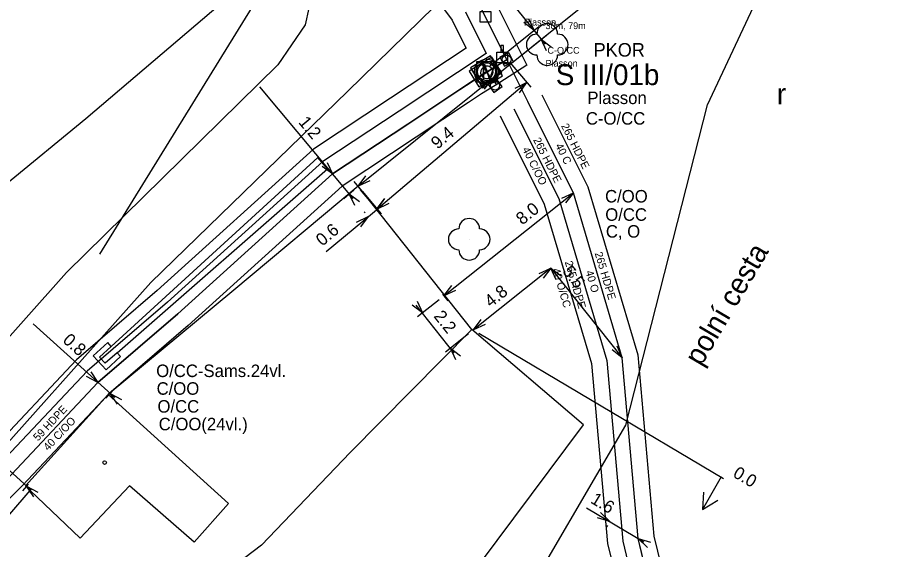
# Model space of a CAD drawing. Extents: x -836739 to -834468, y -1071001 to -1070126.
# Drawn here: x -836480.21 to -836438.65, y -1070294.18 to -1070268.59 of the extents above; entities that cross this region are included whole.
import ezdxf

# ---------------------------------------------------------------- set-up
doc = ezdxf.new("R2010")
doc.units = 0
for name, color, linetype in [('f001_pol_linie', 7, 'Continuous'), ('f001_pol_texty', 7, 'Continuous'), ('f001_pol_znacky', 7, 'Continuous'), ('f002_inz_linie_mimo_CETIN', 7, 'Continuous'), ('f003_opt_sit_texty', 7, 'Continuous'), ('f003_opt_sit_znacky', 7, 'Continuous'), ('f006_kbv_texty', 7, 'Continuous'), ('f006_kbv_znacky', 7, 'Continuous'), ('f006_osa_trasy', 7, 'Continuous'), ('f006_stp_koty', 7, 'Continuous'), ('f006_stp_znacky', 7, 'Continuous'), ('f309_opticka_spojka', 7, 'Continuous'), ('f309_opticka_spojka_ann', 7, 'Continuous'), ('f309_trubka', 7, 'Continuous'), ('f309_trubka_ann', 7, 'Continuous'), ('f309_trubkova_spojka', 7, 'Continuous'), ('f309_trubkova_spojka_ann', 7, 'Continuous'), ('f311_komora_obrys', 7, 'Continuous')]:
    doc.layers.add(name, color=color, linetype=linetype)

msp = doc.modelspace()

# ---------------------------------------------------------------- linework, layer by layer
at = {"layer": 'f001_pol_linie'}
for points in [[(-836463.13, -1070260.78), (-836461.66, -1070261.68), (-836460.5, -1070262.24), (-836459.09, -1070262.17), (-836456.22, -1070259.67), (-836453.89, -1070261.93), (-836464.34, -1070272.16), (-836473.79, -1070281.33)], [(-836490.71, -1070260.96), (-836485.67, -1070268.85), (-836480.77, -1070276.62), (-836476.92, -1070273.45)], [(-836463.13, -1070260.78), (-836466.54, -1070263.19), (-836466.2, -1070265.91), (-836466.63, -1070266.39), (-836466.02, -1070267.34), (-836466.37, -1070268.96), (-836467.68, -1070270.88), (-836477.85, -1070280.85), (-836486.39, -1070290.44)], [(-836356.62, -1070406.87), (-836370.19, -1070399.44), (-836385.43, -1070392.2), (-836396.38, -1070386.03), (-836404.41, -1070381.11), (-836409.87, -1070376.61), (-836425.28, -1070363.93), (-836449.03, -1070345.44), (-836455, -1070340), (-836462.64, -1070329.11), (-836464.81, -1070325.47), (-836465.74, -1070321.03), (-836464.89, -1070314.87), (-836461.62, -1070306.74), (-836456.41, -1070297.54), (-836450.95, -1070288.2), (-836447.03, -1070272.79), (-836441.38, -1070260.76)], [(-836476.92, -1070273.45), (-836467.63, -1070265.54), (-836467.99, -1070264.84), (-836468.56, -1070264.02)], [(-836475.41, -1070284.71), (-836465.3, -1070275.87), (-836465.76, -1070275.33), (-836475.69, -1070284.41)], [(-836463.82, -1070276.71), (-836469.8, -1070281.7)], [(-836458.36, -1070283.6), (-836463.82, -1070276.71)], [(-836473.79, -1070281.33), (-836483.18, -1070291.85), (-836486.04, -1070295.25), (-836496.69, -1070306.07), (-836498.64, -1070308.92), (-836508.98, -1070315.34), (-836516.87, -1070318.79), (-836525.05, -1070322.08), (-836528.75, -1070323.23)], [(-836469.8, -1070281.7), (-836475.84, -1070286.72)], [(-836483.95, -1070318.68), (-836480.18, -1070324.33), (-836477.38, -1070322.05), (-836462.13, -1070300.43), (-836452.98, -1070288.18), (-836458.36, -1070283.6)], [(-836458.36, -1070283.6), (-836464.21, -1070289.51), (-836468.46, -1070293.96), (-836471.67, -1070296.39)], [(-836475.86, -1070284.22), (-836476.56, -1070284.86), (-836475.94, -1070285.54), (-836475.24, -1070284.9), (-836475.41, -1070284.71), (-836475.98, -1070285.22), (-836476.25, -1070284.92), (-836475.69, -1070284.41), (-836475.86, -1070284.22)], [(-836475.84, -1070286.72), (-836470.06, -1070291.96), (-836471.71, -1070293.81), (-836474.82, -1070291.1), (-836477.18, -1070293.62), (-836479.59, -1070291.33), (-836479.82, -1070291.11)], [(-836475.84, -1070286.72), (-836479.82, -1070291.11)], [(-836481.56, -1070293.61), (-836479.59, -1070291.33)]]:
    msp.add_lwpolyline(points, dxfattribs=at)
at = {"layer": 'f001_pol_znacky'}
for centre, radius in [((-836454.73, -1070269.9), 0.0005), ((-836458.48, -1070279.26), 0.0005), ((-836476.01, -1070289.99), 0.0875)]:
    msp.add_circle(centre, radius, dxfattribs=at)
for centre, start, end in [((-836454.73, -1070269.4), 0, 180), ((-836455.23, -1070269.9), 90, 270), ((-836454.23, -1070269.9), 270, 90), ((-836454.73, -1070270.4), 180, 360), ((-836458.48, -1070278.76), 0, 180), ((-836458.98, -1070279.26), 90, 270), ((-836457.98, -1070279.26), 270, 90), ((-836458.48, -1070279.76), 180, 360)]:
    msp.add_arc(centre, 0.5, start, end, dxfattribs=at)
at = {"layer": 'f002_inz_linie_mimo_CETIN'}
msp.add_lwpolyline([(-836466.85, -1070264.73), (-836476.26, -1070279.97)], dxfattribs=at)
at = {"layer": 'f003_opt_sit_znacky'}
msp.add_line((-836457.962, -1070270.697), (-836457.338, -1070271.723), dxfattribs=at)
msp.add_lwpolyline([(-836458.13, -1070271.69), (-836457.17, -1070271.69), (-836457.17, -1070270.73), (-836458.13, -1070270.73)], close=True, dxfattribs=at)
msp.add_circle((-836457.65, -1070271.21), 0.432, dxfattribs=at)
for start, end in [(121.31, 301.31), (301.31, 121.31)]:
    msp.add_arc((-836457.65, -1070271.21), 0.6, start, end, dxfattribs=at)
at = {"layer": 'f006_kbv_znacky'}
msp.add_lwpolyline([(-836457.838, -1070271.983), (-836456.877, -1070271.398), (-836457.462, -1070270.437), (-836458.423, -1070271.022)], close=True, dxfattribs=at)
at = {"layer": 'f006_osa_trasy'}
for points in [[(-836456.68, -1070270.62), (-836458.02, -1070267.94), (-836465.2, -1070258.28), (-836471.29, -1070247.06)], [(-836457.65, -1070271.21), (-836456.68, -1070270.62)], [(-836259.51, -1070422.49), (-836273.33, -1070418.13), (-836279.63, -1070415.33), (-836305.65, -1070405.26), (-836332.15, -1070395.46), (-836355.51, -1070386.15), (-836363.32, -1070381.37), (-836370.68, -1070374.62), (-836386.63, -1070361.4), (-836412.6, -1070344.19), (-836444.52, -1070318.16), (-836450.35, -1070293.64), (-836451.12, -1070284.95), (-836453.47, -1070277.02), (-836456.68, -1070270.62)], [(-836457.65, -1070271.21), (-836461.44, -1070273.73), (-836465.05, -1070276.12), (-836472.49, -1070282.84), (-836476.33, -1070286.14), (-836480.49, -1070290.56), (-836484.46, -1070294.49), (-836485.91, -1070295.8), (-836486.17, -1070297), (-836486.38, -1070297.88), (-836489.6, -1070301.51), (-836494.07, -1070306.05), (-836498.93, -1070309.99), (-836500.26, -1070310.81)]]:
    msp.add_lwpolyline(points, dxfattribs=at)
at = {"layer": 'f006_stp_koty'}
for points in [[(-836456.971, -1070267.218), (-836454.834, -1070269.88)], [(-836463.82, -1070276.709), (-836452.717, -1070267.795)], [(-836455.624, -1070268.655), (-836455.366, -1070269.217), (-836455.858, -1070268.843)], [(-836457.485, -1070270.918), (-836455.132, -1070269.029)], [(-836457.158, -1070271.361), (-836454.788, -1070269.458)], [(-836454.763, -1070270.207), (-836455.022, -1070269.646), (-836454.529, -1070270.019)], [(-836456.515, -1070270.785), (-836455.526, -1070271.953)], [(-836462.931, -1070277.827), (-836455.72, -1070271.724)], [(-836457.953, -1070271.806), (-836457.392, -1070271.548), (-836457.765, -1070272.04)], [(-836457.393, -1070271.547), (-836457.204, -1070271.782)], [(-836456.274, -1070271.997), (-836455.72, -1070271.724), (-836456.081, -1070272.226)], [(-836464.061, -1070277.302), (-836468.547, -1070271.936)], [(-836465.318, -1070275.562), (-836465.049, -1070276.119), (-836465.548, -1070275.754)], [(-836463.258, -1070276.45), (-836463.82, -1070276.709), (-836463.446, -1070276.216)], [(-836463.147, -1070277.547), (-836464.008, -1070276.475)], [(-836464.515, -1070277.291), (-836464.023, -1070276.879)], [(-836463.983, -1070277.628), (-836464.253, -1070277.072), (-836463.753, -1070277.436)], [(-836463.726, -1070276.888), (-836462.737, -1070278.056)], [(-836463.627, -1070276.94), (-836462.712, -1070278.035)], [(-836459.698, -1070281.978), (-836453.47, -1070277.019)], [(-836454.032, -1070277.275), (-836453.47, -1070277.019), (-836453.845, -1070277.51)], [(-836462.376, -1070277.553), (-836462.931, -1070277.827), (-836462.569, -1070277.324)], [(-836462.347, -1070277.534), (-836462.904, -1070277.804), (-836462.539, -1070277.304)], [(-836465.352, -1070279.851), (-836462.674, -1070277.612)], [(-836463.483, -1070277.992), (-836463.53, -1070277.936)], [(-836463.893, -1070278.435), (-836463.337, -1070278.166), (-836463.701, -1070278.665)], [(-836454.551, -1070280.641), (-836458.28, -1070283.609)], [(-836455.113, -1070280.897), (-836454.551, -1070280.641), (-836454.926, -1070281.132)], [(-836454.551, -1070280.641), (-836451.12, -1070284.95)], [(-836454.294, -1070281.203), (-836454.551, -1070280.641), (-836454.059, -1070281.016)], [(-836459.135, -1070281.721), (-836459.698, -1070281.978), (-836459.322, -1070281.486)], [(-836459.932, -1070282.164), (-836460.966, -1070282.987)], [(-836459.759, -1070281.901), (-836459.511, -1070282.213)], [(-836460.987, -1070282.237), (-836460.731, -1070282.8), (-836461.222, -1070282.424)], [(-836459.199, -1070284.725), (-836461.033, -1070282.422)], [(-836475.52, -1070286.87), (-836479.442, -1070283.33)], [(-836457.717, -1070283.352), (-836458.28, -1070283.609), (-836457.904, -1070283.117)], [(-836458.514, -1070283.796), (-836459.62, -1070284.677)], [(-836458.022, -1070283.763), (-836446.257, -1070290.752)], [(-836459.129, -1070285.052), (-836459.386, -1070284.49), (-836458.894, -1070284.865)], [(-836451.376, -1070284.387), (-836451.12, -1070284.95), (-836451.611, -1070284.574)], [(-836476.674, -1070285.626), (-836476.33, -1070286.14), (-836476.875, -1070285.849)], [(-836475.946, -1070286.895), (-836475.542, -1070286.446)], [(-836475.398, -1070287.182), (-836475.743, -1070286.669), (-836475.197, -1070286.959)], [(-836479.537, -1070291.321), (-836482.506, -1070288.641)], [(-836446.37, -1070290.67), (-836447.26, -1070292.25)], [(-836479.683, -1070291.034), (-836479.961, -1070291.342)], [(-836479.415, -1070291.633), (-836479.76, -1070291.12), (-836479.214, -1070291.41)], [(-836447.21, -1070291.41), (-836447.26, -1070292.25), (-836446.52, -1070291.8)], [(-836452.842, -1070292.159), (-836450.092, -1070293.793)], [(-836452.161, -1070292.388), (-836451.722, -1070292.824), (-836452.314, -1070292.646)], [(-836451.835, -1070293.013), (-836451.876, -1070293.082)], [(-836449.91, -1070294.075), (-836450.35, -1070293.64), (-836449.757, -1070293.817)]]:
    msp.add_lwpolyline(points, dxfattribs=at)
at = {"layer": 'f006_stp_znacky'}
for points in [[(-836457.952, -1070268.318), (-836457.448, -1070268.318), (-836457.448, -1070268.822), (-836457.952, -1070268.822)], [(-836457.152, -1070270.268), (-836456.648, -1070270.268), (-836456.648, -1070270.772), (-836457.152, -1070270.772)]]:
    msp.add_lwpolyline(points, close=True, dxfattribs=at)
msp.add_lwpolyline([(-836456.837, -1070270.268), (-836456.837, -1070269.953), (-836456.963, -1070269.953), (-836456.963, -1070270.268)], dxfattribs=at)
msp.add_circle((-836457.65, -1070271.21), 0.5, dxfattribs=at)
at = {"layer": 'f309_opticka_spojka'}
msp.add_line((-836457.793, -1070270.979), (-836457.477, -1070271.489), dxfattribs=at)
for start, end in [(301.8576, 121.8576), (121.8576, 301.8576)]:
    msp.add_arc((-836457.635, -1070271.234), 0.3, start, end, dxfattribs=at)
at = {"layer": 'f309_trubka'}
for points in [[(-836470.632, -1070246.7), (-836470.273, -1070247.361), (-836464.566, -1070257.875), (-836457.379, -1070267.546), (-836455.708, -1070270.887), (-836457.239, -1070271.869)], [(-836457.635, -1070271.234), (-836456.68, -1070270.62), (-836458.02, -1070267.94), (-836465.2, -1070258.28), (-836470.932, -1070247.719), (-836471.29, -1070247.06)], [(-836466.468, -1070259.09), (-836459.302, -1070268.728), (-836458.973, -1070269.389), (-836458.634, -1070270.069), (-836462.269, -1070272.48), (-836465.972, -1070274.932), (-836473.482, -1070281.714), (-836477.368, -1070285.054), (-836481.564, -1070289.512), (-836485.491, -1070293.4), (-836487.006, -1070294.77), (-836495.142, -1070304.988), (-836499.8, -1070308.764), (-836506.642, -1070312.996), (-836515.474, -1070317.594), (-836521.802, -1070319.876), (-836532.34, -1070323.572), (-836539.962, -1070325.81), (-836542.393, -1070326.52), (-836543.113, -1070326.73), (-836550.512, -1070328.89)], [(-836458.661, -1070268.334), (-836457.667, -1070270.328), (-836461.855, -1070273.105), (-836465.511, -1070275.526), (-836472.986, -1070282.277), (-836476.849, -1070285.597), (-836481.027, -1070290.036), (-836484.975, -1070293.945), (-836486.458, -1070295.285), (-836494.606, -1070305.519), (-836499.365, -1070309.377), (-836506.271, -1070313.648), (-836515.172, -1070318.282), (-836521.551, -1070320.583), (-836532.11, -1070324.286), (-836539.751, -1070326.53), (-836542.183, -1070327.24), (-836542.903, -1070327.45), (-836550.286, -1070329.605)], [(-836500.259, -1070310.812), (-836498.93, -1070309.99), (-836494.07, -1070306.05), (-836485.91, -1070295.8), (-836484.46, -1070294.49), (-836480.49, -1070290.56), (-836476.33, -1070286.14), (-836472.49, -1070282.84), (-836465.05, -1070276.12), (-836461.44, -1070273.73), (-836458.925, -1070272.058), (-836458.298, -1070271.646), (-836457.635, -1070271.234)], [(-836457.239, -1070271.869), (-836457.883, -1070272.271), (-836458.51, -1070272.683), (-836461.025, -1070274.355), (-836464.589, -1070276.714), (-836471.994, -1070283.403), (-836475.811, -1070286.683), (-836479.953, -1070291.084), (-836483.945, -1070295.035), (-836485.362, -1070296.315), (-836493.534, -1070306.581), (-836498.495, -1070310.603), (-836499.139, -1070311.001)], [(-836454.989, -1070272.319), (-836452.77, -1070276.743), (-836450.38, -1070284.809), (-836449.608, -1070293.52), (-836449.436, -1070294.242), (-836443.91, -1070317.483), (-836412.074, -1070342.908), (-836385.592, -1070360.377), (-836362.275, -1070380.609), (-836354.445, -1070384.979), (-836353.838, -1070385.201), (-836331.612, -1070394.06), (-836305.12, -1070403.858), (-836279.054, -1070413.944), (-836272.798, -1070416.724), (-836261.073, -1070420.421)], [(-836456.329, -1070272.991), (-836454.17, -1070277.297), (-836451.86, -1070285.091), (-836451.092, -1070293.76), (-836445.25, -1070318.333), (-836412.956, -1070344.122), (-836386.5, -1070361.575), (-836363.141, -1070381.843), (-836355.073, -1070386.347), (-836354.374, -1070386.603), (-836332.15, -1070395.46), (-836305.65, -1070405.26), (-836279.63, -1070415.33), (-836273.33, -1070418.13), (-836262.175, -1070421.648)], [(-836261.299, -1070421.137), (-836273.064, -1070417.427), (-836279.342, -1070414.637), (-836305.385, -1070404.559), (-836331.881, -1070394.76), (-836354.106, -1070385.902), (-836354.759, -1070385.663), (-836362.708, -1070381.226), (-836386.046, -1070360.976), (-836412.515, -1070343.515), (-836444.58, -1070317.908), (-836450.178, -1070294.362), (-836450.35, -1070293.64), (-836451.12, -1070284.95), (-836453.47, -1070277.02), (-836455.659, -1070272.655)], [(-836457, -1070273.327), (-836454.87, -1070277.574), (-836452.6, -1070285.232), (-836451.834, -1070293.88), (-836451.663, -1070294.602), (-836445.92, -1070318.758), (-836413.397, -1070344.729), (-836386.954, -1070362.174), (-836363.574, -1070382.46), (-836355.387, -1070387.031), (-836354.642, -1070387.304), (-836332.419, -1070396.16), (-836305.915, -1070405.961), (-836279.918, -1070416.023), (-836273.596, -1070418.833), (-836262.401, -1070422.363)]]:
    msp.add_lwpolyline(points, dxfattribs=at)
at = {"layer": 'f309_trubkova_spojka'}
for points in [[(-836456.573, -1070270.298), (-836457.002, -1070270.513), (-836456.787, -1070270.942), (-836456.358, -1070270.727)], [(-836457.187, -1070271.534), (-836457.574, -1070271.817), (-836457.291, -1070272.204), (-836456.904, -1070271.921)]]:
    msp.add_lwpolyline(points, close=True, dxfattribs=at)
for centre in [(-836456.68, -1070270.62), (-836457.239, -1070271.869)]:
    msp.add_circle(centre, 0.216, dxfattribs=at)
at = {"layer": 'f311_komora_obrys'}
msp.add_lwpolyline([(-836458.48, -1070271.18), (-836458.013, -1070271.932), (-836456.919, -1070271.252), (-836457.386, -1070270.5)], close=True, dxfattribs=at)

# ---------------------------------------------------------------- texts
at = {"layer": 'f001_pol_texty'}
msp.add_text('polní cesta', height=1, rotation=59.5876, dxfattribs=at).set_placement((-836447.33, -1070285.41))
at = {"layer": 'f001_pol_znacky'}
msp.add_text('r', height=1, dxfattribs=at).set_placement((-836443.688, -1070272.772))
at = {"layer": 'f003_opt_sit_texty'}
for s, height, p in [('S III/01b', 1, (-836454.32, -1070271.85)), ('Plasson', 0.6, (-836452.8, -1070272.76)), ('C-O/CC', 0.6, (-836452.87, -1070273.75)), ('C/OO', 0.6, (-836451.95, -1070277.49)), ('O/CC', 0.6, (-836451.94, -1070278.37)), ('C, O', 0.6, (-836451.91, -1070279.18)), ('O/CC-Sams.24vl.', 0.6, (-836473.53, -1070285.88)), ('C/OO', 0.6, (-836473.51, -1070286.73)), ('O/CC', 0.6, (-836473.47, -1070287.59)), ('C/OO(24vl.)', 0.6, (-836473.41, -1070288.44))]:
    msp.add_text(s, height=height, dxfattribs=at).set_placement(p)
at = {"layer": 'f006_kbv_texty'}
msp.add_text('PKOR', height=0.65, dxfattribs=at).set_placement((-836452.5, -1070270.48))
at = {"layer": 'f006_stp_koty'}
for s, rotation, p in [('1.2', 309.89, (-836466.723, -1070273.647)), ('9.4', 40.24, (-836460.005, -1070274.959)), ('8.0', 38.53, (-836455.934, -1070278.599)), ('0.6', 39.9, (-836465.544, -1070279.62)), ('5.5', 308.53, (-836454.031, -1070280.811)), ('4.8', 38.53, (-836457.446, -1070282.563)), ('2.2', 308.53, (-836460.216, -1070282.967)), ('0.8', 317.93, (-836478.066, -1070284.166)), ('0.0', 329.29, (-836445.845, -1070290.647)), ('1.6', 329.29, (-836452.688, -1070291.901))]:
    msp.add_text(s, height=0.6, rotation=rotation, dxfattribs=at).set_placement(p)
at = {"layer": 'f006_stp_znacky'}
msp.add_text('M', height=0.75, dxfattribs=at).set_placement((-836457.916, -1070271.585))
at = {"layer": 'f309_opticka_spojka_ann'}
msp.add_text('30m, 79m', height=0.325, dxfattribs=at).set_placement((-836454.812, -1070269.158))
at = {"layer": 'f309_trubka_ann'}
for s, rotation, p in [('265 HDPE', 296.6375, (-836454.075, -1070273.806)), ('265 HDPE', 296.6289, (-836455.416, -1070274.478)), ('40 C/OO', 296.6289, (-836455.942, -1070274.935)), ('40 C', 296.6375, (-836454.353, -1070274.758)), ('265 HDPE', 286.51, (-836452.452, -1070279.928)), ('265 HDPE', 286.511, (-836453.889, -1070280.354)), ('40 O/CC', 286.511, (-836454.488, -1070280.711)), ('40 O', 286.51, (-836452.892, -1070280.816)), ('59 HDPE', 46.7357, (-836479.212, -1070288.983)), ('40 C/OO', 46.7357, (-836478.725, -1070289.451))]:
    msp.add_text(s, height=0.375, rotation=rotation, dxfattribs=at).set_placement(p)
at = {"layer": 'f309_trubkova_spojka_ann'}
for s, p in [('Plasson', (-836455.846, -1070268.986)), ('C-O/CC', (-836454.719, -1070270.34)), ('Plasson', (-836454.811, -1070270.965))]:
    msp.add_text(s, height=0.325, dxfattribs=at).set_placement(p)

doc.saveas('drawing.dxf')
